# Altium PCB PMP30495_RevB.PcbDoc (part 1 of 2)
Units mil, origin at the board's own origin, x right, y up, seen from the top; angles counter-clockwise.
Board outline 6212.5 x 2387.5 mil, 2 copper layers (Top Layer, Bottom Layer), stack 62 mil thick; 95 components, 48 nets, 204 pads, 17 vias.
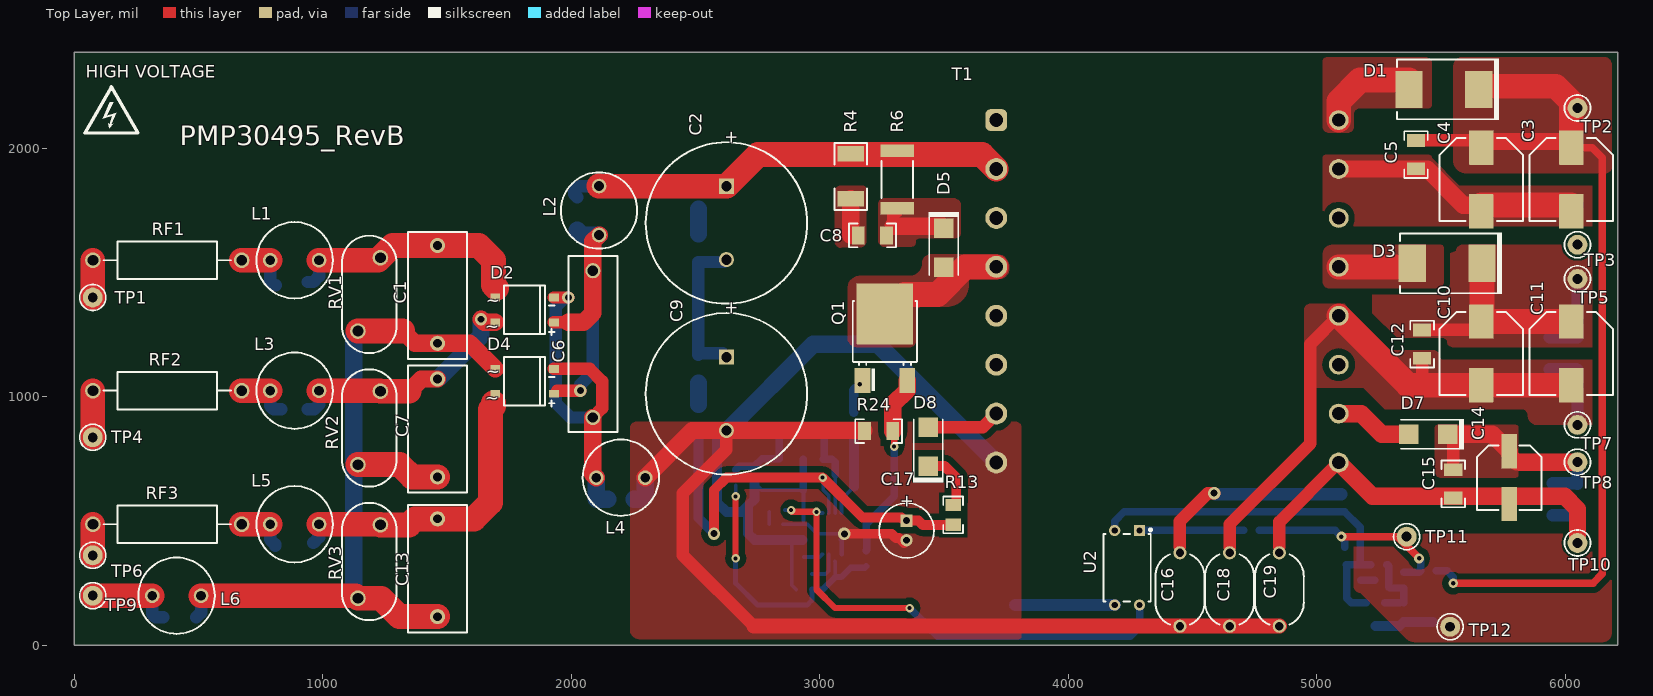
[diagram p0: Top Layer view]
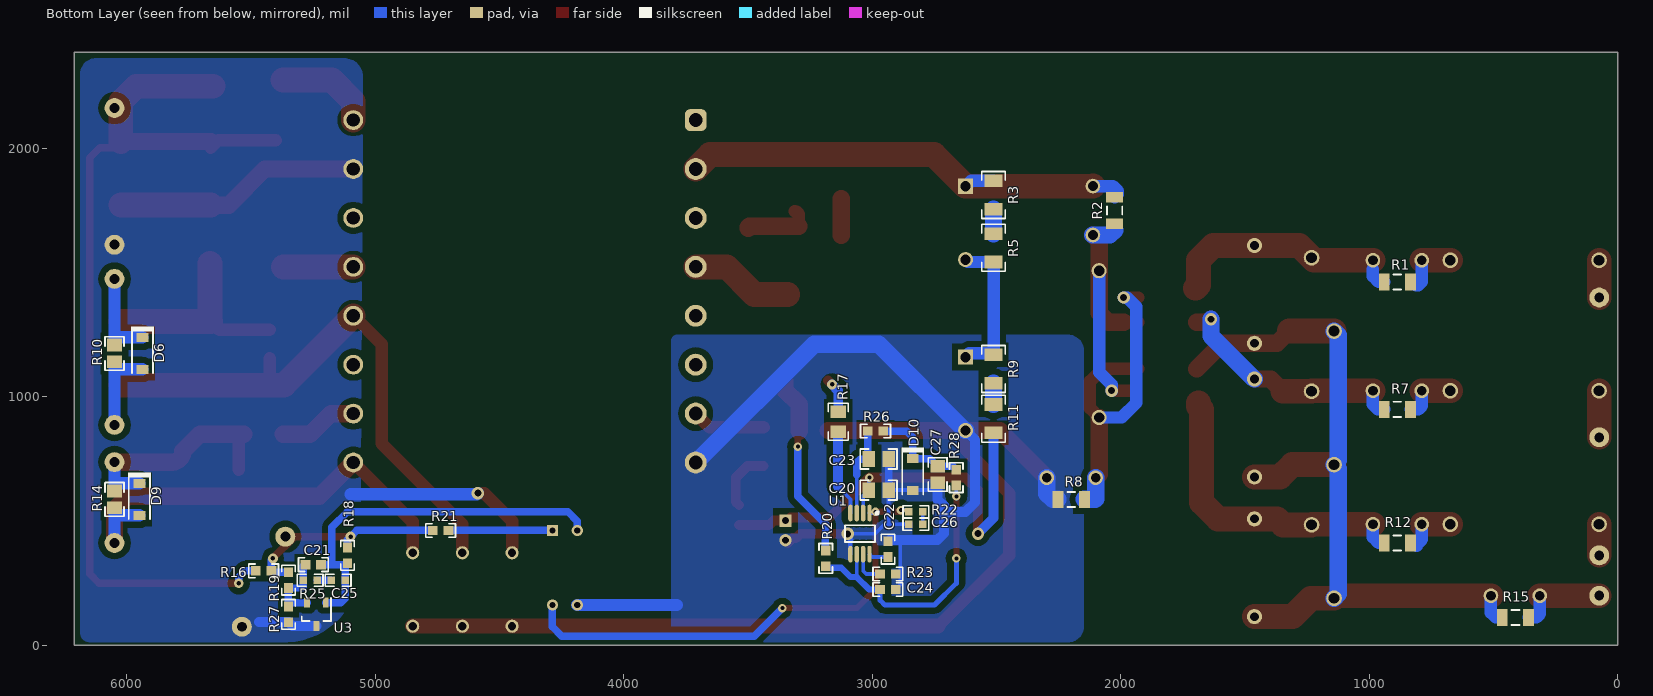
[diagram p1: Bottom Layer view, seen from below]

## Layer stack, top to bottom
Top Solder: solder mask 0.4, Solder Resist, Dk 3.5
Top Layer: signal copper 1.4
Dielectric1: core 59.2, FR-4, Dk 4.8
Bottom Layer: signal copper 1.4
Bottom Solder: solder mask 0.4, Solder Resist, Dk 3.5

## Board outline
0,0 6212.5,0 6212.5,2387.5 0,2387.5

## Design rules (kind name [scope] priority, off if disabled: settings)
AcuteAngle [All] p1: minimum=4.50000000000000E+0001 checktracksonly=FALSE
AssemblyTestPointUsage [All] p1: valid=2
BoardOutlineClearance BoardOutlineClearance_MountingHoles [OnCopper and InComponentClass('Mounting Holes')] p1: gap=10 ignorepadtopadclearanceinfootprint=FALSE
BoardOutlineClearance BoardOutlineClearance_Poly [OnCopper and IsPoly] p2: gap=10 ignorepadtopadclearanceinfootprint=FALSE
BoardOutlineClearance [OnCopper and Not InComponentClass('Logo') and not InComponentClass('FiducialMark') and not InRegion(1000,500,4000,800) and not InPoly] p3: gap=20 ignorepadtopadclearanceinfootprint=FALSE
Clearance "Schematic Clearance Constraint" [InNet('NetC6_1')] p1: gap=25 ignorepadtopadclearanceinfootprint=FALSE except(0: Arc-Hole Track-Hole SMDPad-Hole THPad-Hole Via-Hole Fill-Hole Poly-Hole Region-Hole Text-Hole)
Clearance Clearance_1 [InNet('PGND')] p2: gap=25 ignorepadtopadclearanceinfootprint=FALSE except(7.5: Arc-SMDPad Track-SMDPad; 15: SMDPad-SMDPad)
Clearance Clearance_Keepouts [((IsTrack Or IsArc) And Not InPoly) And IsFree and IsKeepOut vs ((IsTrack Or IsArc) And Not InPoly) And IsFree and IsKeepOut] p3: gap=0 ignorepadtopadclearanceinfootprint=FALSE
Clearance Clearance_Poly [InPolygon] p4: gap=25 ignorepadtopadclearanceinfootprint=FALSE except(0: Arc-Hole Track-Hole SMDPad-Hole THPad-Hole Via-Hole Fill-Hole Poly-Hole Region-Hole Text-Hole)
Clearance Clearance_FiducialMark [IsKeepOut and InComponentClass('FiducialMark') vs IsPad and InComponentClass('FiducialMark')] p5: gap=0 ignorepadtopadclearanceinfootprint=FALSE
Clearance [All] p6: gap=7.87 ignorepadtopadclearanceinfootprint=FALSE except(0: Arc-Hole Track-Hole SMDPad-Hole THPad-Hole Via-Hole Fill-Hole Poly-Hole Region-Hole Text-Hole)
ComponentClearance ComponentClearance_MountingHoles_FiducialMarks [InComponentClass('Mounting Holes') vs InComponentClass('FiducialMark')] p1: gap=20 collisioncheckmode=3 verticalgap=10 showdistances=FALSE
ComponentClearance ComponentClearance_Shunt [InComponentClass('Header') vs InComponentClass('Shunt')] p2: gap=0 collisioncheckmode=3 verticalgap=0 showdistances=FALSE
ComponentClearance ComponentClearance_Logo [InComponentClass('Logo')] p3: gap=20 collisioncheckmode=3 verticalgap=10 showdistances=FALSE
ComponentClearance ComponentClearance_ScrewToNut [(HasFootprint('NY PMS 440 0025 PH')) vs (HasFootprint('Keystone_1902C'))] p4: gap=5 collisioncheckmode=3 verticalgap=10 showdistances=FALSE
ComponentClearance ComponentClearance_MountingHoles [InComponentClass('Mounting Holes')] p5: gap=20 collisioncheckmode=3 verticalgap=100000 showdistances=FALSE
ComponentClearance ComponentClearance_SmallPassives [HasFootprint('0201*') or HasFootprint('0402*') or HasFootprint('0508') or HasFootprint('0603*') or HasFootprint('0612') or HasFootprint('0805*') or HasFootprint('0815*') or HasFootprint('0830*') or HasFootprint('1206*') or HasFootprint('1210*') or HasFootprint('1808*') or HasFootprint('1812*') or HasFootprint('1825*') or HasFootprint('2010*') or HasFootprint('2220*') or HasFootprint('2225*') or HasFootprint('2512*') or HasFootprint('2728*') or HasFootprint('3518*') vs HasFootprint('0201*') or HasFootprint('0402*') or HasFootprint('0508') or HasFootprint('0603*') or HasFootprint('0612') or HasFootprint('0805*') or HasFootprint('0815*') or HasFootprint('0830*') or HasFootprint('1206*') or HasFootprint('1210*') or HasFootprint('1808*') or HasFootprint('1812*') or HasFootprint('1825*') or HasFootprint('2010*') or HasFootprint('2220*') or HasFootprint('2225*') or HasFootprint('2512*') or HasFootprint('2728*') or HasFootprint('3518*')] p6: gap=10 collisioncheckmode=3 verticalgap=10 showdistances=FALSE
ComponentClearance ComponentClearance_THtoSMT [IsThruComponent vs IsSMTComponent] p7: gap=20 collisioncheckmode=3 verticalgap=20 showdistances=FALSE
ComponentClearance ComponentClearance_THtoTH [IsThruComponent vs IsThruComponent] p8: gap=20 collisioncheckmode=3 verticalgap=20 showdistances=FALSE
ComponentClearance [All] p9: gap=20 collisioncheckmode=3 verticalgap=10 showdistances=FALSE
DiffPairsRouting [All] p1: maxlimit=100 minlimit=10 mostfreqgap=10 toplayer_minwidth=15 toplayer_maxwidth=15 toplayer_prefwidth=15 bottomlayer_minwidth=15 bottomlayer_maxwidth=15 bottomlayer_prefwidth=15 maxuncoupledlength=1000
FabricationTestPointUsage TestPointUsage [All] p1: valid=2 allowmultiple=FALSE
FabricationTestpoint Testpoint [All] p1: side=3 testpointundercomponent=TRUE minsize=40 maxsize=100 preferedsize=60 minholesize=0 maxholesize=40 preferedholesize=32 testpointgrid=1 allowsidetop=TRUE allowsidebottom=TRUE usegrid=TRUE gridtolerance=0.01
FanoutControl Fanout_LCC [IsLCC] p1: bgadir=Out bgaviamode=Centered fanoutstyle=Auto fanoutdirection=Alternating viagrid=1 // Fanout_LCC (Default Rule)
FanoutControl Fanout_BGA [IsBGA] p2: bgadir=Out bgaviamode=Centered fanoutstyle=Auto fanoutdirection=Alternating viagrid=1 // Fanout_BGA (Default Rule)
FanoutControl Fanout_Default [All] p4: bgadir=Out bgaviamode=Centered fanoutstyle=Auto fanoutdirection=Alternating viagrid=1 // Fanout_Default (Default Rule)
FanoutControl Fanout_Small [(CompPinCount < 5)] p5: bgadir=Out bgaviamode=Centered fanoutstyle=Auto fanoutdirection=OutThenIn viagrid=1 // Fanout_Small (Default Rule)
Height [All] p1: minheight=0 maxheight=2000 prefheight=500
HoleSize [All] p1: absolutevalues=TRUE maxlimit=251 minlimit=7.87 maxpercent=80.000 minpercent=20.000
MinimumAnnularRing MinimumAnnularRing_ThermalPadVias [IsVia and InAnyComponent] p1: minimumring=5.91
MinimumAnnularRing [All] p2: minimumring=8
MinimumSolderMaskSliver MinimumSolderMaskSliver_Logo [InComponentClass('Logo') vs InComponentClass('Logo')] p1: minsoldermaskwidth=0.7
MinimumSolderMaskSliver [All] p2: minsoldermaskwidth=3.94
PlaneConnect [All] p1: planeconnectstyle=Relief reliefexpansion=10 reliefentries=4 reliefconductorwidth=10 reliefairgap=10
PolygonConnect [All] p1: connectstyle=Direct reliefconductorwidth=10 reliefentries=4 polygonreliefangle="90 Angle" airgapwidth=10
RoutingVias ThermalPadVias [IsVia and InAnyComponent] p1: holewidth=7.87 width=19.68 viastyle="Through Hole" minholewidth=7.87 minwidth=19.68 maxholewidth=12.99 maxwidth=23.62
RoutingVias [All] p2: holewidth=16 width=34 viastyle="Through Hole" minholewidth=7.87 minwidth=26 maxholewidth=40 maxwidth=65
SilkToBoardRegionClearance [Not ((IsComment or IsDesignator) And (Hide <> 'False')) and not InRegion(1000,500,4000,800)] p1:
SilkToSilkClearance SilkToSilkClearance_Pb-FreeLogo [(HasFootprint('Pb-Free_Overlay_Medium') OR HasFootprint('Pb-Free_Overlay_Small')) vs (HasFootprint('Pb-Free_Overlay_Medium') OR HasFootprint('Pb-Free_Overlay_Small'))] p1: silktosilkclearance=0
SilkToSilkClearance [All] p2: silktosilkclearance=0
SilkToSolderMaskClearance SilkToComponentPadClearance [(IsPad or IsFill or IsRegion) and InAnycomponent] p1: minsilkscreentomaskgap=0 clearancetoexposedcopper=TRUE
SilkToSolderMaskClearance "Silk to Solder Mask Opening" [All] p2: minsilkscreentomaskgap=0 clearancetoexposedcopper=FALSE
SolderMaskExpansion [All] p1: expansion=1.97
Width [All] p1: maxlimit=100 minlimit=6 preferedwidth=10 checkconnectedcopper=TRUE
14 further rules are at their usual default settings.

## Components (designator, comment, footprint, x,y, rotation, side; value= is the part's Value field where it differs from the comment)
C1 "B32921C3104M" B32921_1300x1200x600 1462.5,1412.5 r270 top value=0.1uF
C2 "UVK2V470MHD" VR_1600x2500 2625,1700 r270 top value=47uF
C3 "UWG1E680MNL1GS" Nichicon_800x1000 6025,1875 r270 top value=68uF
C4 "UWG1E680MNL1GS" Nichicon_800x1000 5662.5,1875 r270 top value=68uF
C5 "Used in BOM report" 1206 5400,1975 r270 top value=TBD
C6 "B32652A0103K" B32652A_500x1050x1800 2087.5,1212.5 r270 top value=0.01uF
C7 "B32921C3104M" B32921_1300x1200x600 1462.5,875 r270 top value=0.1uF
C8 "GRM31BR73A102KW01L" 1206 3212.5,1650 r0 top value=1000pF
C9 "UVK2V470MHD" VR_1600x2500 2625,1012.5 r270 top value=47uF
C10 "UWG1E680MNL1GS" Nichicon_800x1000 5662.5,1175 r270 top value=68uF
C11 "UWG1E680MNL1GS" Nichicon_800x1000 6025,1175 r270 top value=68uF
C12 "Used in BOM report" 1206 5425,1212.5 r270 top value=TBD
C13 "B32921C3104M" B32921_1300x1200x600 1462.5,312.5 r270 top value=0.1uF
C14 "UUD1H100MCL1GS" SM_RADIAL_6.3AMM 5775,675 r270 top value=10uF
C15 "Used in BOM report" 1206 5550,650 r270 top value=TBD
C16 "VY2102M29Y5UG63V7" CAPRD750W60D750H1050 4450,225 r270 top value=1000pF
C17 "UPW1V100MDD6" PW_500x700 3350,462.5 r270 top value=10uF
C18 "VY2102M29Y5UG63V7" CAPRD750W60D750H1050 4650,225 r270 top value=1000pF
C19 "VY2102M29Y5UG63V7" CAPRD750W60D750H1050 4850,225 r270 top value=1000pF
C20 "08055C105KAT2A" 0805_HV 2975,625 r180 bottom value=1uF
C21 "GRM188R71H472KA01D" 0603 5250,325 r180 bottom value=4700pF
C22 "GRM188R71H104KA93D" 0603 2937.5,387.5 r90 bottom value=0.1uF
C23 "08055C105KAT2A" 0805_HV 2975,750 r180 bottom value=1uF
C24 "C0603C221K5RACTU" 0603 2937.5,225 r180 bottom value=220pF
C25 "Used in BOM report" 0603_HV 5150,262.5 r0 bottom value=TBD
C26 "Used in BOM report" 0603_HV 2825,487.5 r0 bottom value=DNP
C27 "Used in BOM report" 0805 2737.5,687.5 r270 bottom value=DNP
D1 "30BQ150" SMC 5512.5,2237.5 r180 top
D2 "MB8S-TP" MBS-1 1812.5,1350 r180 top value=800V
D3 "30BQ150" SMC 5525,1537.5 r180 top
D4 "MB8S-TP" MBS-1 1812.5,1062.5 r180 top value=800V
D5 "US1K-13-F" SMA 3500,1600 r270 top value=800V
D6 "MMSZ5245B-7-F" SOD-123 5937.5,1175 r270 bottom value=15V
D7 "MURA140T3G" SMA 5450,850 r180 top value=400V
D8 "ES1C-13-F" SMA 3437.5,800 r90 top value=150V
D9 "MMSZ5258B-7-F" SOD-123 5950,587.5 r270 bottom value=36V
D10 "Used in BOM report" SOD-123 2837.5,687.5 r270 bottom value=DNP
"HIGH VOLTAGE" "DANGER HIGH VOLTAGE" IEC_HighVoltage_Small 150,2150 r0 top
L1 "744772471" WE_TI_8095_Unshielded 887.5,1550 r0 top value=470uH
L2 "744772471" WE_TI_8095_Unshielded 2112.5,1750 r90 top value=470uH
L3 "744772471" WE_TI_8095_Unshielded 887.5,1025 r0 top value=470uH
L4 "744772471" WE_TI_8095_Unshielded 2200,675 r0 top value=470uH
L5 "744772471" WE_TI_8095_Unshielded 887.5,487.5 r0 top value=470uH
L6 "744772471" WE_TI_8095_Unshielded 412.5,200 r0 top value=470uH
Q1 "IPD90R1K2C3ATMA1" DPAK 3262.5,1200 r90 top value=900V
R1 "CRCW120610K0JNEA" 1206L 887.5,1462.5 r0 bottom value=10k
R2 "CRCW120610K0JNEA" 1206L 2025,1750 r90 bottom value=10k
R3 "Used in BOM report" 1206 2512.5,1812.5 r90 bottom
R4 "CRCW201040R2FKEF" 2010 3125,1887.5 r90 top value=40.2
R5 "Used in BOM report" 1206 2512.5,1600 r90 bottom
R6 "CRCW2512200KFKE" 2512 3312.5,1875 r90 top value=200k
R7 "CRCW120610K0JNEA" 1206L 887.5,950 r0 bottom value=10k
R8 "CRCW120610K0JNEA" 1206L 2200,587.5 r0 bottom value=10k
R9 "Used in BOM report" 1206 2512.5,1112.5 r90 bottom
R10 "Used in BOM report" 0805 6050,1175 r90 bottom value=DNP
R11 "Used in BOM report" 1206 2512.5,912.5 r90 bottom
R12 "CRCW120610K0JNEA" 1206L 887.5,412.5 r0 bottom value=10k
R13 "CRCW080510R0FKEA" 0805_HV 3537.5,525 r90 top value=10.0
R14 "Used in BOM report" 0805 6050,587.5 r90 bottom value=DNP
R15 "CRCW120610K0JNEA" 1206L 412.5,112.5 r0 bottom value=10k
R16 "CRCW060349R9FKEA" 0603 5450,300 r0 bottom value=49.9
R17 "CRCW08050000Z0EA" 0805_HV 3137.5,900 r90 bottom value=0
R18 "Used in BOM report" 0603 5112.5,362.5 r90 bottom value=DNP
R19 "CRCW0603100KFKEA" 0603 5350,262.5 r90 bottom value=100k
R20 "CRCW06031K00FKEA" 0603 3187.5,350 r90 bottom value=1.00k
R21 "CRCW06034K99FKEA" 0603 4737.5,462.5 r0 bottom value=4.99k
R22 "Used in BOM report" 0603_HV 2825,537.5 r0 bottom value=DNP
R23 "CRCW060366K5FKEA" 0603 2937.5,287.5 r0 bottom value=66.5k
R24 "ERJ-8RQF1R0V" 1206 3237.5,862.5 r0 top value=1.00
R25 "Used in BOM report" 0603_HV 5262.5,262.5 r180 bottom value=TBD
R26 "Used in BOM report" 0603 2987.5,862.5 r0 bottom value=DNP
R27 "CRCW060326K1FKEA" 0603 5350,125 r90 bottom value=26.1k
R28 "Used in BOM report" 0603 2662.5,675 r270 bottom value=DNP
RF1 "SPP1UL1R00JLF" SPP_1020x380 375,1550 r180 top value=1.0
RF2 "SPP1UL1R00JLF" SPP_1020x380 375,1025 r180 top value=1.0
RF3 "SPP1UL1R00JLF" SPP_1020x380 375,487.5 r180 top value=1.0
RV1 "B72210S2301K101" EPCOS_B72210S2301K101 1187.5,1412.5 r90 top value=300VAC
RV2 "B72210S2301K101" EPCOS_B72210S2301K101 1187.5,875 r90 top value=300VAC
RV3 "B72210S2301K101" EPCOS_B72210S2301K101 1187.5,337.5 r90 top value=300VAC
T1 "750317812" Wurth_750317812 4400,1425 r0 top value=1.5mH
TP1 "5000" Keystone5000 75,1400 r0 top
TP2 "5000" Keystone5000 6050,2162.5 r90 top
TP3 "5001" Keystone5001 6050,1612.5 r90 top
TP4 "5000" Keystone5000 75,837.5 r90 top
TP5 "5000" Keystone5000 6050,1475 r270 top
TP6 "5000" Keystone5000 75,362.5 r90 top
TP7 "5001" Keystone5001 6050,887.5 r270 top
TP8 "5000" Keystone5000 6050,737.5 r90 top
TP9 "5000" Keystone5000 75,200 r90 top
TP10 "5001" Keystone5001 6050,412.5 r90 top
TP11 "5000" Keystone5000 5362.5,437.5 r90 top value=Red
TP12 "5001" Keystone5001 5537.5,75 r90 top value=Black
U1 "LM5021MM-1/NOPB" MUA08A_N 3050,450 r270 bottom
U2 "FOD817A" DIP-4 4237.5,312.5 r270 top
U3 "ATL431AIDBZR" DBZ0003A_N 5237.5,125 r270 bottom

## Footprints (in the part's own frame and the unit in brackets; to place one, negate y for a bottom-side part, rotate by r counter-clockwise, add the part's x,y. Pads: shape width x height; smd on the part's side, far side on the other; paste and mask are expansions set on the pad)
0603 [mm] "0603 from SM-752 data"
  rect 1x0.95 smd: 1(-0.8,0) 2(0.8,0)
  silkscreen extent -1.52,-0.69 1.52,0.69, body extent -0.87,-0.47 0.87,0.47, height 1
0603_HV [mil] "Ernesto recommended land pattern.  26 mil between pads."
  rect 30x30 smd: 1(-28,0) 2(28,0)
  silkscreen extent -52,-24 52,24, body extent -34,-19 34,19, height 39
0805 [mm] "0805 from SM-752 data"
  rect 1.3x1.5 smd: 1(-0.85,0) 2(0.85,0)
  silkscreen extent -1.72,-0.97 1.72,0.97, body extent -1.1,-0.72 1.1,0.72, height 1.45
0805_HV [mil] "0805 with 30mil clearance between pads"
  rect 50x63 smd: 1(-40,0) 2(40,0)
  silkscreen extent -74,-40 74,40, body extent -43,-29 43,29, height 57
1206 [mm] "1206 from SM-752 data"
  rect 1.3x1.85 smd: 1(-1.45,0) 2(1.45,0)
  silkscreen extent -2.4,-1.21 2.4,1.21, body extent -1.7,-0.9 1.7,0.9, height 1.35
1206L [mm] "1206 from SM-752 data"
  rect 1.1x1.75 smd: 1(-1.35,0) 2(1.35,0)
  silkscreen extent -0.4,-0.77 0.4,0.77, body extent -1.7,-0.9 1.7,0.9, height 1.35
2010 [mm] "Chip Capacitor, Body 5.08x2.54mm, IPC Medium Density"
  rect 1.6x2.7 smd: 1(-2.3,0) 2(2.3,0)
  silkscreen extent -3.42,-1.65 3.42,1.65, body extent -2.73,-1.45 2.73,1.45, height 1.66
2512 [mm] "Chip Resistor, Body 6.3x3.2mm, IPC Medium Density"
  rect 1.3x3.4 smd: 1(-2.95,0) 2(2.95,0)
  silkscreen extent -1.9,-1.6 1.9,1.6, body extent -3.22,-1.67 3.22,1.67, height 0.71
B32652A_500x1050x1800 [mm] "THD, 2-Leads, Body 18x5mm, Height 10.5mm"
  round 1.55 hole 1.05: 1(-7.5,0) 2(7.5,0)
  silkscreen extent -9,-2.5 9,2.5, body extent -9,-2.5 9,2.5, height 10.5
B32921_1300x1200x600 [mm] "EPCOS"
  round 1.55 hole 0.9: 1(-5,0) 2(5,0)
  silkscreen extent -6.4,-3 6.6,3, body extent -6.4,-3 6.6,3, height 12
CAPRD750W60D750H1050 [mm] "Vishay BC Components"
  round 1.35 hole 0.85: 1(-3.75,0) 2(3.75,0)
  silkscreen extent -3.6,-2.51 3.6,2.51, body extent -4.15,-2.5 4.15,2.5, height 11.25
DBZ0003A_N [mm] "SOT23, 3-Leads, Body 2.9x1.3mm, Pitch 0.95mm, Lead Span 2.4mm, IPC Medium Density"
  rrect17% 1x0.6 smd: 1(-1.2,0.95) 2(-1.2,-0.95) 3(1.2,0)
  silkscreen extent -1.65,-1.5 0.7,1.5, body extent -1.26,-1.46 1.26,1.46, height 0.98
DIP-4 [mm] "DIP, 4-Leads, Body 6.86x4.83mm, Pitch 2.54mm"
  rect 1.15x1.15 hole 0.65: 1(-3.81,1.27)
  round 1.15 hole 0.65: 2(-3.81,-1.27) 3(3.81,-1.27) 4(3.81,1.27)
  silkscreen extent -4,-2.41 3.43,2.52, body extent -4.02,-2.41 4.02,2.41, height 5.59
DPAK [mm] "D-PAK, 3-Pads, Body 6.22x6.73mm (max), TO-252AA using nominal STEP model"
  rrect6% 2.6x1.6 smd: 1(-3.4,2.28) 3(-3.4,-2.28)
  rrect2% 6.2x5.8 smd paste-2.9: 4(3.4,0)
  silkscreen extent -4.5,-3.3 4.7,3.28, body extent -3.86,-3.29 5.84,3.29, height 2.48
EPCOS_B72210S2301K101 [mm] "Through Hole Varistor, 2-Leads, Body 12x5.6mm, Height 14.5mm"
  round 1.6 hole 1.1: 1(-3.75,1.15) 2(3.75,-1.15)
  silkscreen extent -6,-2.8 6,2.8, body extent -5.95,-2.8 6,2.8, height 14.49
IEC_HighVoltage_Small [mil]
  silkscreen extent -107,-88 107,97
Keystone5000 [mil] "For Keystone 500x miniature loop terminals"
  round 80 hole 40: 1(0,0)
  silkscreen extent -52,-52 52,52, body extent -49,-49 49,49, height 182
Keystone5001 [mil] "For Keystone 500x miniature loop terminals"
  round 80 hole 40: 1(0,0)
  silkscreen extent -52,-52 52,52, body extent -49,-49 49,49, height 182
MBS-1 [mm] "SOP, 4-Leads, Body 4.95x4.2mm"
  rect 1x0.8 smd: 1(-3,1.27) 2(3,1.27) 3(3,-1.27) 4(-3,-1.27)
  silkscreen extent -3.08,-2.48 2.1,2.56, body extent -3.45,-2.47 3.45,2.48, height 2.9
MUA08A_N [mm] "TSOP, 8-Leads, Body 3x3mm, Pitch 0.65mm, IPC Medium Density"
  oval 1.7x0.45 smd: 1(-2.1,0.975) 2(-2.1,0.325) 3(-2.1,-0.325) 4(-2.1,-0.975) 5(2.1,-0.975) 6(2.1,-0.325) 7(2.1,0.325) 8(2.1,0.975)
  silkscreen extent -2.22,-1.55 0.85,1.87, body extent -1.6,-1.6 1.6,1.6, height 1.09
Nichicon_800x1000 [mm] "SMD, 2-Leads, Dia 8mm"
  rrect4% 3.5x2.5 smd: 1(-3.25,0) 2(3.25,0)
  silkscreen extent -4.25,-4.25 4.25,4.25, body extent -4.25,-4.25 4.25,4.25, height 10.81
PW_500x700 [mm] "Nichicon"
  rect 1.25x1.25 hole 0.711: 1(-1,0)
  round 1.25 hole 0.711: 2(1,0)
  silkscreen extent -2.8,-2.8 2.8,2.8, body extent -2.73,-2.75 2.75,2.75, height 8.01
SM_RADIAL_6.3AMM [mm] "Nichicon 6.3x5.8"
  rect 3.5x1.6 smd: 1(-2.7,0) 2(2.7,0)
  silkscreen extent -3.3,-3.29 3.3,3.31, body extent -3.5,-3.3 3.5,3.3, height 6.11
SMA [mm] "Molded Diode, 2-Leads, Body 4.3x2.6mm, IPC Medium Density, based on OnSemi component dimensions and land pattern"
  rect 2x2 smd: 1(-2,0) 2(2,0)
  silkscreen extent -3.66,-1.57 2.79,1.57, body extent -2.6,-1.3 2.6,1.3, height 2.42
SMC [mil] "Molded Diode, 2-Leads, Body 6.9x5.8mm, IPC Medium Density, based on OnSemi component dimensions and land patterns"
  rect 110x150 smd: 1(-140.49,0) 2(140.49,0)
  silkscreen extent -221,-124 189,123, body extent -156,-116 156,116, height 91
SOD-123 [mm] "On Semi recommended land pattern"
  rect 0.915x1.22 smd: 1(-1.637,0) 2(1.637,0)
  silkscreen extent -2.74,-1.17 2.03,1.17, body extent -1.93,-0.9 1.93,0.9, height 1.35
SPP_1020x380 [mm] "TH, 2-Leads, Axial, Dia 3.8mm, Pin Spaing 15.2mm"
  round 1.6 hole 1.1: 1(-7.6,0) 2(7.6,0)
  silkscreen extent -6.53,-1.9 6.53,1.9, body extent -8,-1.88 8,1.9, height 3.8
VR_1600x2500 [mm] "TH, 2-Leads, Dia 16mm, Pin Spacing 7.5mm"
  rect 1.55x1.55 hole 1.05: 1(-3.75,0)
  round 1.55 hole 1.05: 2(3.75,0)
  silkscreen extent -8.25,-8.25 8.25,8.25, body extent -8.19,-8.24 8.23,8.24, height 27.01
WE_TI_8095_Unshielded [mm] "TH, 2-Leads, Dia 7.8mm, Pin Spacing 5mm"
  round 1.5 hole 1: 1(-2.5,0) 2(2.5,0)
  silkscreen extent -3.9,-3.9 3.9,3.9, body extent -5.52,-5.52 5.52,5.52, height 9.5
Wurth_750317812 [mm] "TH, 16-Leads, Body 44.5x41.5mm, Pitch 5mm"
  rrect50% 2.24x2.24 hole 1.4: 1(-17.5,17.5)
  round 2.24 hole 1.4: 2(-17.5,12.5) 3(-17.5,7.5) 4(-17.5,2.5) 5(-17.5,-2.5) 6(-17.5,-7.5) 7(-17.5,-12.5) 8(-17.5,-17.5)
  round 2.025 hole 1.35: 9(17.5,-17.5) 10(17.5,-12.5) 11(17.5,-7.5) 12(17.5,-2.5) 13(17.5,2.5) 14(17.5,7.5) 15(17.5,12.5) 16(17.5,17.5)
  body extent -22.25,-20.75 22.25,20.75, height 30

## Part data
C1 C7 C13: "CAP, Film, 0.1uF, 305V, +/-20%, TH", Cap_Case=13x12x6mm, Manufacturer="EPCOS Inc", Supplier Part Number 1=495-2318-ND, Tolerance_%=20, Value1=Unknown, Value2=305V, ValueDisplayed=0.1µF
C2 C9: library part CMP-0082581-1, "CAP, AL, 47 µF, 350 V, +/- 20%, TH", Cap_Case=16x25mm, Manufacturer=Nichicon, Supplier Part Number 1=493-16356-ND, Tolerance_%=20%, Value2=350V, ValueDisplayed=47µF
C3 C4 C10 C11: library part CMP-0082582-1, "CAP, AL, 68 µF, 25 V, +/- 20%, SMD", Cap_Case=8x10mm, Manufacturer=Nichicon, Supplier Part Number 1=493-6315-1-ND, Tolerance_%=20%, Value2=25V, ValueDisplayed=68µF
C5 C12 C15 C25 C26 C27: library part Capacitor, "CAP, CERM, xxxF, xxV, [TempCo], xx%, [PackageReference]", Alternate Manufacturer=-
C6: "CAP, Film, 0.01uF, 1000V, +/-10%, TH", Cap_Case=5x10.5x18, Manufacturer="EPCOS Inc", Tolerance_%=10, Value1=Unknown, Value2=1000V, ValueDisplayed="0.01 µF"
C8: "CAP, CERM, 1000 pF, 1000 V,+/- 10%, X7R, 1206", Cap_Case=1206, Manufacturer=MuRata, Supplier Part Number 1=490-3494-1-ND, TempCo=X7R, Tolerance_%=10, Value2=1000V, ValueDisplayed=1000pF
C14: library part CMP-0011413-2, "CAP, AL, 10 uF, 50 V, +/- 20%, 0.88 ohm, SMD", Cap_Case=6.3x5.8, Manufacturer=Nichicon, Supplier Part Number 1=493-2298-1-ND, Tolerance_%=20%, Value1="0.88 ohm", Value2=50V, ValueDisplayed=10uF
C16 C18 C19: "CAP, CERM, 1000pF, 300V, +/-20%, Y5U, Radial Disc 7.5mm, ls=7.5", Cap_Case="Radial Disc 7.5mm, ls{}7.5", Manufacturer=Vishay-Bccomponents, Supplier Part Number 1=BC2752-ND, TempCo=Y5U, Tolerance_%=20, Value1=Unknown, Value2=300V, ValueDisplayed=1000pF
C17: "CAP, AL, 10 µF, 35 V, +/- 20%, 0.95 ohm, TH", Cap_Case=5x7, Manufacturer=Nichicon, Supplier Part Number 1=493-1850-ND, Tolerance_%=20, Value1="0.95 ohm", Value2=35V, ValueDisplayed=10µF
C20: "CAP, CERM, 1 µF, 50 V,+/- 10%, X7R, 0805", Cap_Case=0805, Manufacturer=AVX, Supplier Part Number 1=478-7956-1-ND, TempCo=X7R, Tolerance_%=10, Value2=50V, ValueDisplayed=1µF
C21: "CAP, CERM, 4700 pF, 50 V,+/- 10%, X7R, 0603", Cap_Case=0603, Manufacturer=MuRata, Supplier Part Number 1=490-1506-1-ND, TempCo=X7R, Tolerance_%=10, Value2=50V, ValueDisplayed=4700pF
C22: "CAP, CERM, 0.1 µF, 50 V,+/- 10%, X7R, 0603", Cap_Case=0603, Manufacturer=MuRata, Supplier Part Number 1=490-1519-1-ND, TempCo=X7R, Tolerance_%=10, Value2=50V, ValueDisplayed=0.1µF
C23: "CAP, CERM, 1 µF, 50 V, +/- 10%, X7R, 0805", Cap_Case=0805, Manufacturer=AVX, Supplier Part Number 1=478-7956-1-ND, TempCo=X7R, Tolerance_%=10, Value1=Unknown, Value2=50V, ValueDisplayed=1µF
C24: "CAP, CERM, 220 pF, 50 V,+/- 10%, X7R, 0603", Cap_Case=0603, Manufacturer=Kemet, Supplier Part Number 1=399-1071-1-ND, TempCo=X7R, Tolerance_%=10, Value2=50V, ValueDisplayed=220pF
D1 D3: library part Diode_Schottky, "Diode, Schottky, 150V, xxA, [PackageReference]", Alternate Manufacturer=-, Manufacturer="Used in BOM report"
D2 D4: "Diode, Switching-Bridge, 800V, 0.5A, 4-Pin TO269AA, Body 4.95 x 4.2 mm, Pitch 2.555 mm", Manufacturer="Micro Commercial Components", Supplier Part Number 1=MB8S-TPMSDKR-ND, Value1=0.5A, Value2=1V
D5: "Diode, Fast Rectifier, 800 V, 1 A, SMA", Manufacturer="Diodes Inc.", Supplier Part Number 1=US1K-FDICT-ND, Value1=1A, Value2=1.7V
D6: "Diode, Zener, 15 V, 500 mW, SOD-123", Manufacturer="Diodes Inc.", Power_W=0.5, Supplier Part Number 1=MMSZ5245B-FDICT-ND, Value1=0.5W
D7: library part CMP-0029038-1, "Diode, Ultrafast, 400 V, 1 A, SMA", Manufacturer="ON Semiconductor", Supplier Part Number 1=MURA120T3GOSCT-ND, Value1=1A, Value2=0.0875V
D8: library part CMP-0029023-1, "Diode, Superfast Rectifier, 150 V, 1 A, SMA", Manufacturer="Diodes Inc.", Supplier Part Number 1=ES1C-FDICT-ND, Value1=1A, Value2=0.92V
D9: "Diode, Zener, 36 V, 500 mW, SOD-123", Manufacturer="Diodes Inc.", Power_W=0.5, Supplier Part Number 1=MMSZ5258B-FDICT-ND, Value1=0.5W
D10: library part Zener, "Diode, Zener, xxV, xxxmW, [PackageReference]", Alternate Manufacturer=-
"HIGH VOLTAGE": library part IEC_HighVoltage, "IEC 61010-1 High Voltage Warning"
L1 L2 L3 L4 L5 L6: library part 744772221, "Inductor, Wirewound, Ferrite, 470 µH", Manufacturer="Wurth Elektronik", Supplier Part Number 1=732-3777-ND, ValueDisplayed=470µH
Q1: library part CMP-0074794-1, "MOSFET, N-CH, 900 V, 5.1 A, DPAK", Alternate Manufacturer=None, Manufacturer="Infineon Technologies", Supplier Part Number 1=IPD90R1K2C3ATMA1CT-ND, Value1="? ohm", Value2="28 nC"
R1 R2 R7 R8 R12 R15: "RES, 10k ohm, 5%, 0.25W, 1206", Manufacturer=Vishay-Dale, Power_W=0.25, Supplier Part Number 1=541-10KECT-ND, TempCo="200 ppm/C", Tolerance_%=5, Value1=5%, Value2=0.25W, Value_Code=10k0
R3 R5 R9 R10 R11 R14 R18 R22 R25 R26 R28: library part Resistor, "RES, xxx ohm, x%, xW, [PackageReference]", Alternate Manufacturer=-
R4: "RES, 40.2, 1%, 0.75 W, AEC-Q200 Grade 0, 2010", Manufacturer=Vishay-Dale, Power_W=0.75, Supplier Part Number 1=541-40.2ACCT-ND, TempCo="100 ppm/C", Tolerance_%=1, Value1=1%, Value2=0.75W, Value_Code=40R2, ValueDisplayed=40.2
R6: "RES, 200 k, 1%, 1 W, AEC-Q200 Grade 0, 2512", Manufacturer=Vishay-Dale, Power_W=1, Supplier Part Number 1=541-200KAFCT-ND, TempCo="100 ppm/C", Value1=1%, Value2=1W, Value_Code=200k
R13: "RES, 10.0, 1%, 0.125 W, 0805", Manufacturer=Vishay-Dale, Power_W=0.125, Supplier Part Number 1=541-10.0CCT-ND, TempCo="100 ppm/C", Tolerance_%=1, Value1=1%, Value2=0.125W, Value_Code=10R0, ValueDisplayed=10.0
R16: "RES, 49.9, 1%, 0.1 W, 0603", Manufacturer=Vishay-Dale, Power_W=0.1, Supplier Part Number 1=541-49.9HCT-ND, TempCo="100 ppm/C", Tolerance_%=1, Value1=1%, Value2=0.1W, Value_Code=49R9, ValueDisplayed=49.9
R17: "RES, 0, 5%, 0.125 W, 0805", Manufacturer=Vishay-Dale, Power_W=0.125, Supplier Part Number 1=541-0.0ACT-ND, TempCo="200 ppm/C", Tolerance_%=5, Value1=5%, Value2=0.125W, Value_Code=0000, ValueDisplayed=0
R19: "RES, 100 k, 1%, 0.1 W, 0603", Manufacturer=Vishay-Dale, Power_W=0.1, Supplier Part Number 1=541-100KHCT-ND, TempCo="100 ppm/C", Tolerance_%=1, Value1=1%, Value2=0.1W, Value_Code=100k
R20: "RES, 1.00 k, 1%, 0.1 W, 0603", Manufacturer=Vishay-Dale, Power_W=0.1, Supplier Part Number 1=541-1.00KHCT-ND, TempCo="100 ppm/C", Tolerance_%=1, Value1=1%, Value2=0.1W, Value_Code=1k00, ValueDisplayed=1.00k
R21: "RES, 4.99 k, 1%, 0.1 W, 0603", Manufacturer=Vishay-Dale, Power_W=0.1, Supplier Part Number 1=541-4.99KHCT-ND, TempCo="100 ppm/C", Tolerance_%=1, Value1=1%, Value2=0.1W, Value_Code=4k99, ValueDisplayed=4.99k
R23: "RES, 66.5 k, 1%, 0.1 W, 0603", Manufacturer=Vishay-Dale, Power_W=0.1, Supplier Part Number 1=541-66.5KHCT-ND, TempCo="100 ppm/C", Tolerance_%=1, Value1=1%, Value2=0.1W, Value_Code=66k5, ValueDisplayed=66.5k
R24: "RES, 1.00, 1%, 0.25 W, 1206", Manufacturer=Panasonic, Power_W=0.25, Supplier Part Number 1=P1.0RCT-ND, TempCo="200 ppm/C", Tolerance_%=1, Value1=1%, Value2=0.25W, Value_Code=1R00, ValueDisplayed=1.00
R27: "RES, 26.1 k, 1%, 0.1 W, 0603", Manufacturer=Vishay-Dale, Power_W=0.1, Supplier Part Number 1=541-26.1KHCT-ND, TempCo="100 ppm/C", Tolerance_%=1, Value1=1%, Value2=0.1W, Value_Code=26k1, ValueDisplayed=26.1k
RF1 RF2 RF3: "RES, 1.0, 5%, 1 W, TH", Manufacturer="TT Electronics/IRC", Power_W=1, Supplier Part Number 1=989-1255-1-ND, TempCo="300 ppm/C", Tolerance_%=5, Value1=5%, Value2=1W, Value_Code=1R00, ValueDisplayed=1.0
RV1 RV2 RV3: "SIOV Metal Oxide Leaded Varistor, 300VAC, 3500A, TH", Manufacturer="EPCOS Inc", Supplier Part Number 1=495-1434-ND
T1: library part CMP-0083732-1, "Transformer, 1500 uH, TH", Manufacturer="Wurth Elektronik", ValueDisplayed=1.5mH
TP1 TP2 TP4 TP5 TP6 TP8 TP9: "Test Point, Miniature, Red, TH", Color=Red, Manufacturer=Keystone, Supplier Part Number 1=36-5000-ND
TP3 TP7 TP10: "Test Point, Miniature, Black, TH", Color=Black, Manufacturer=Keystone, Supplier Part Number 1=36-5001-ND
TP11: "Test Point, Miniature, Red, TH", Manufacturer=Keystone, Supplier Part Number 1=5000K-ND
TP12: "Test Point, Miniature, Black, TH", Manufacturer=Keystone, Supplier Part Number 1=5001K-ND
U1: "AC-DC Current Mode PWM Controller, 8-pin MSOP, Pb-Free", Manufacturer="Texas Instruments", PackageTopMarking=ZXTT*21-1, PowerWise=N, Supplier Part Number 1=LM5021MM-1TR-ND
U2: "Optocoupler, 5 kV, 80-160% CTR, TH", Manufacturer="Fairchild Semiconductor", Supplier Part Number 1=FOD817A-ND, Voltage_Isolation_Vrms=5000V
